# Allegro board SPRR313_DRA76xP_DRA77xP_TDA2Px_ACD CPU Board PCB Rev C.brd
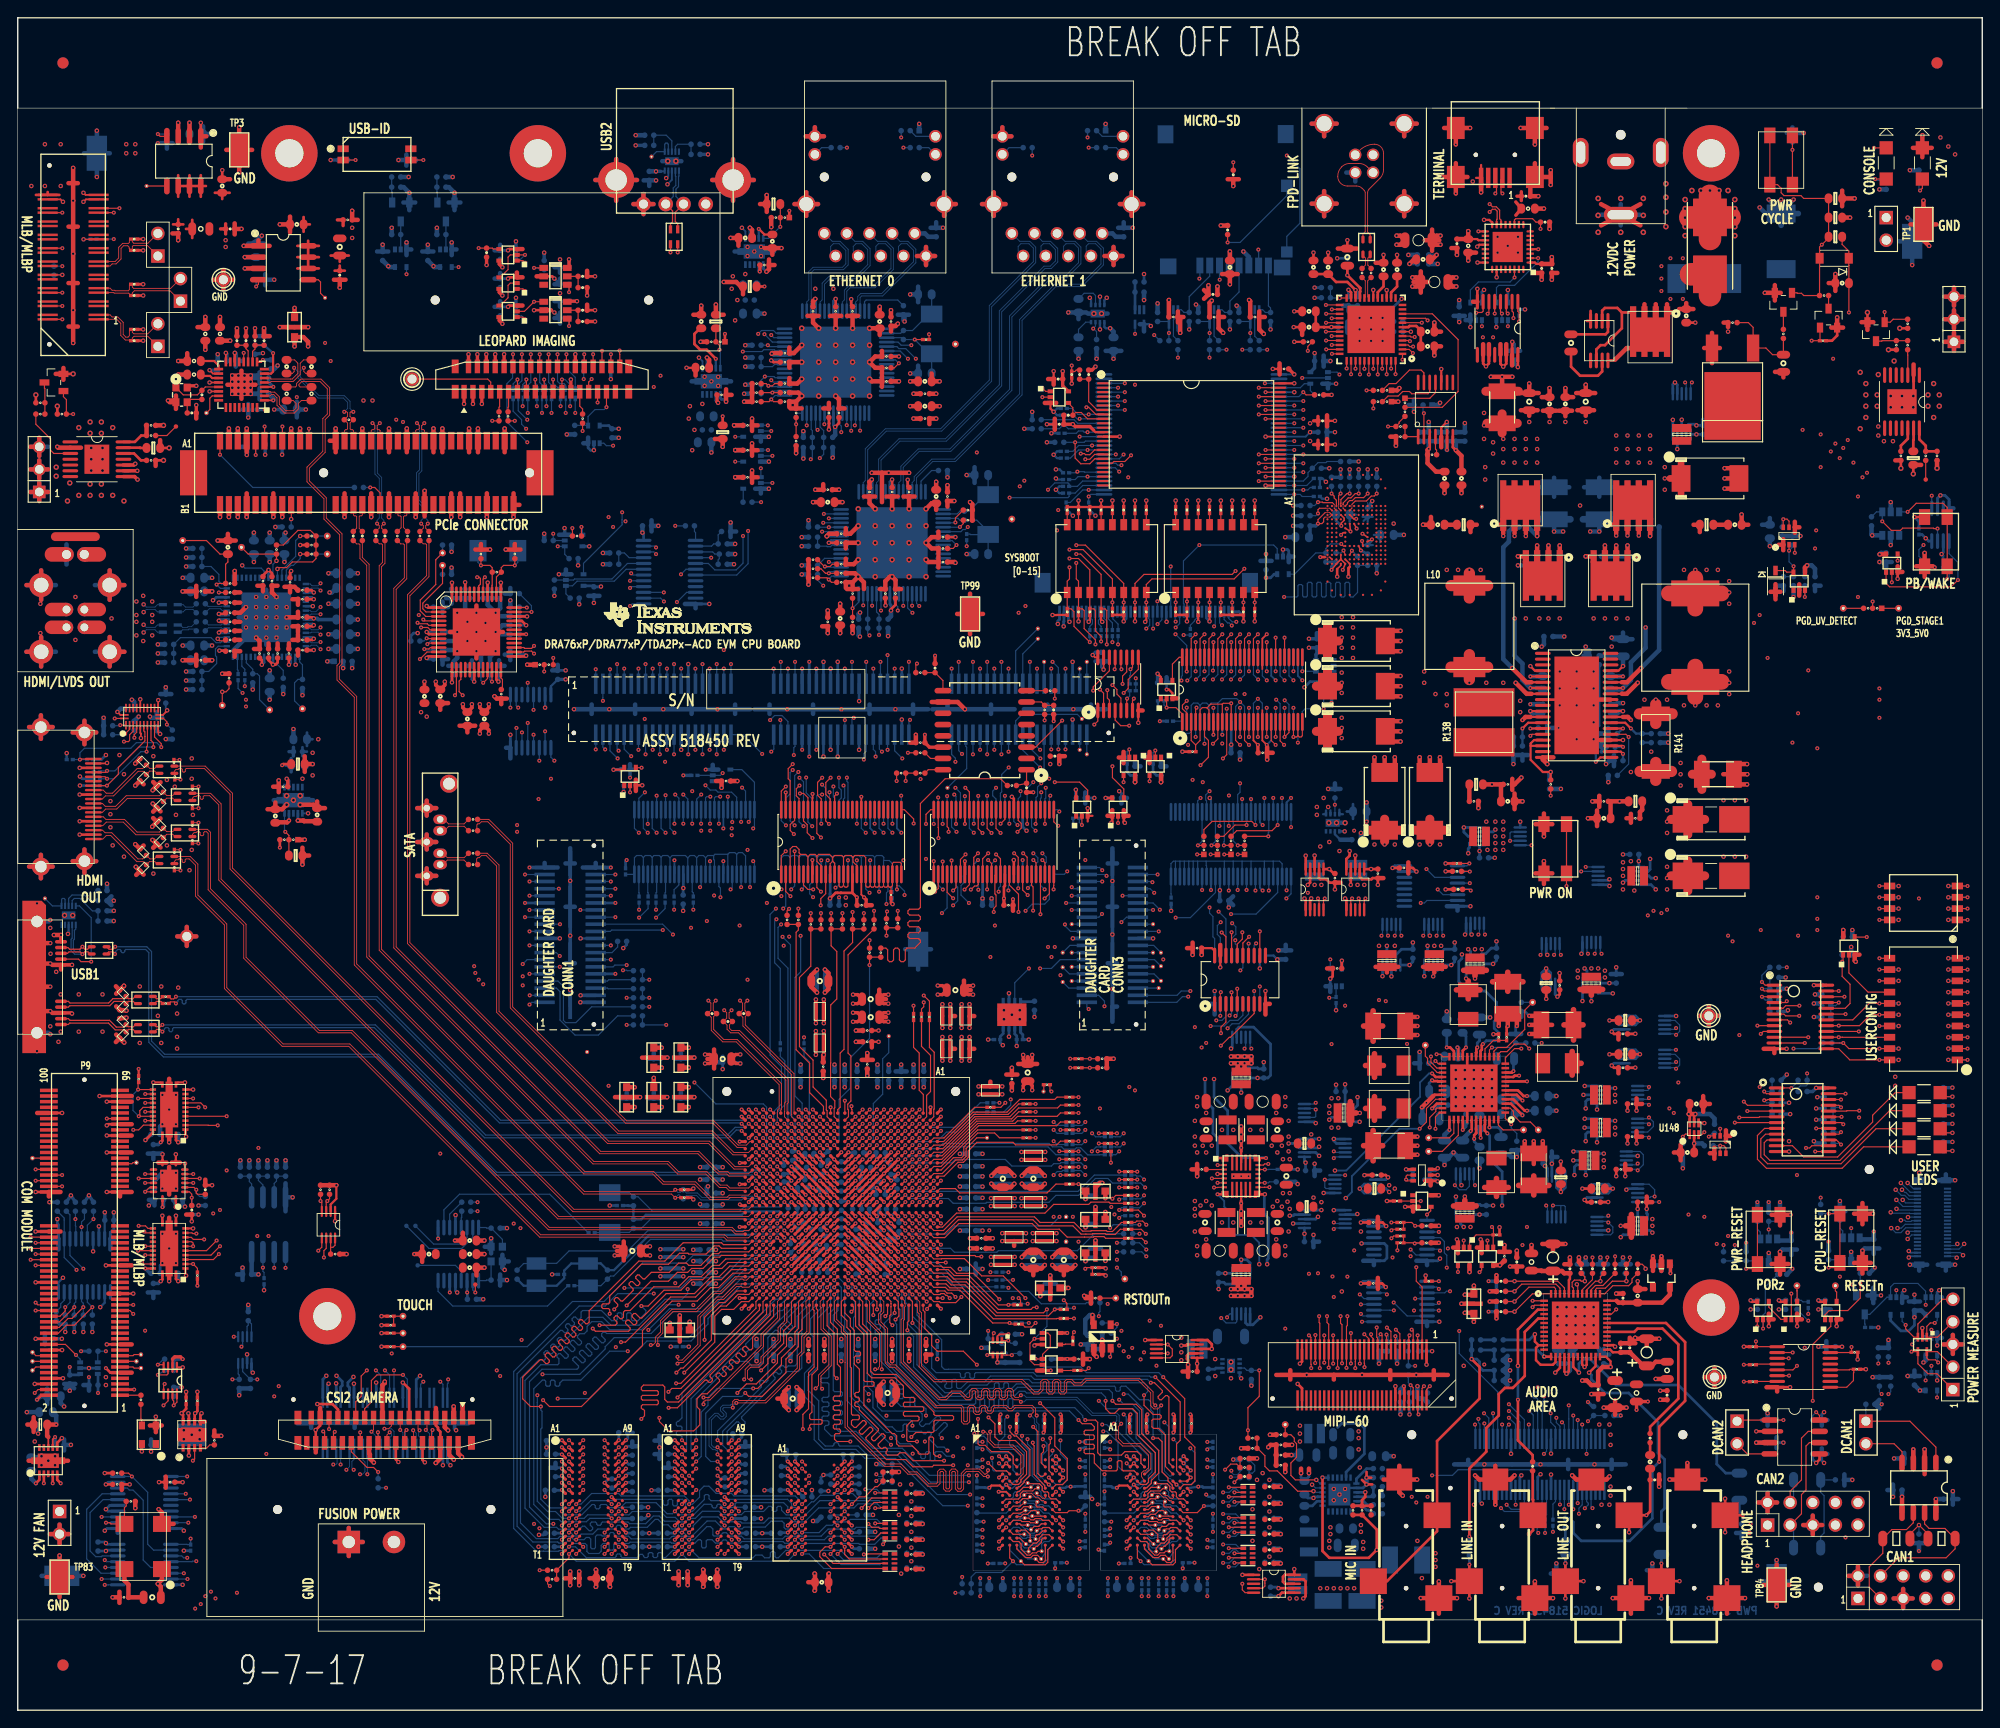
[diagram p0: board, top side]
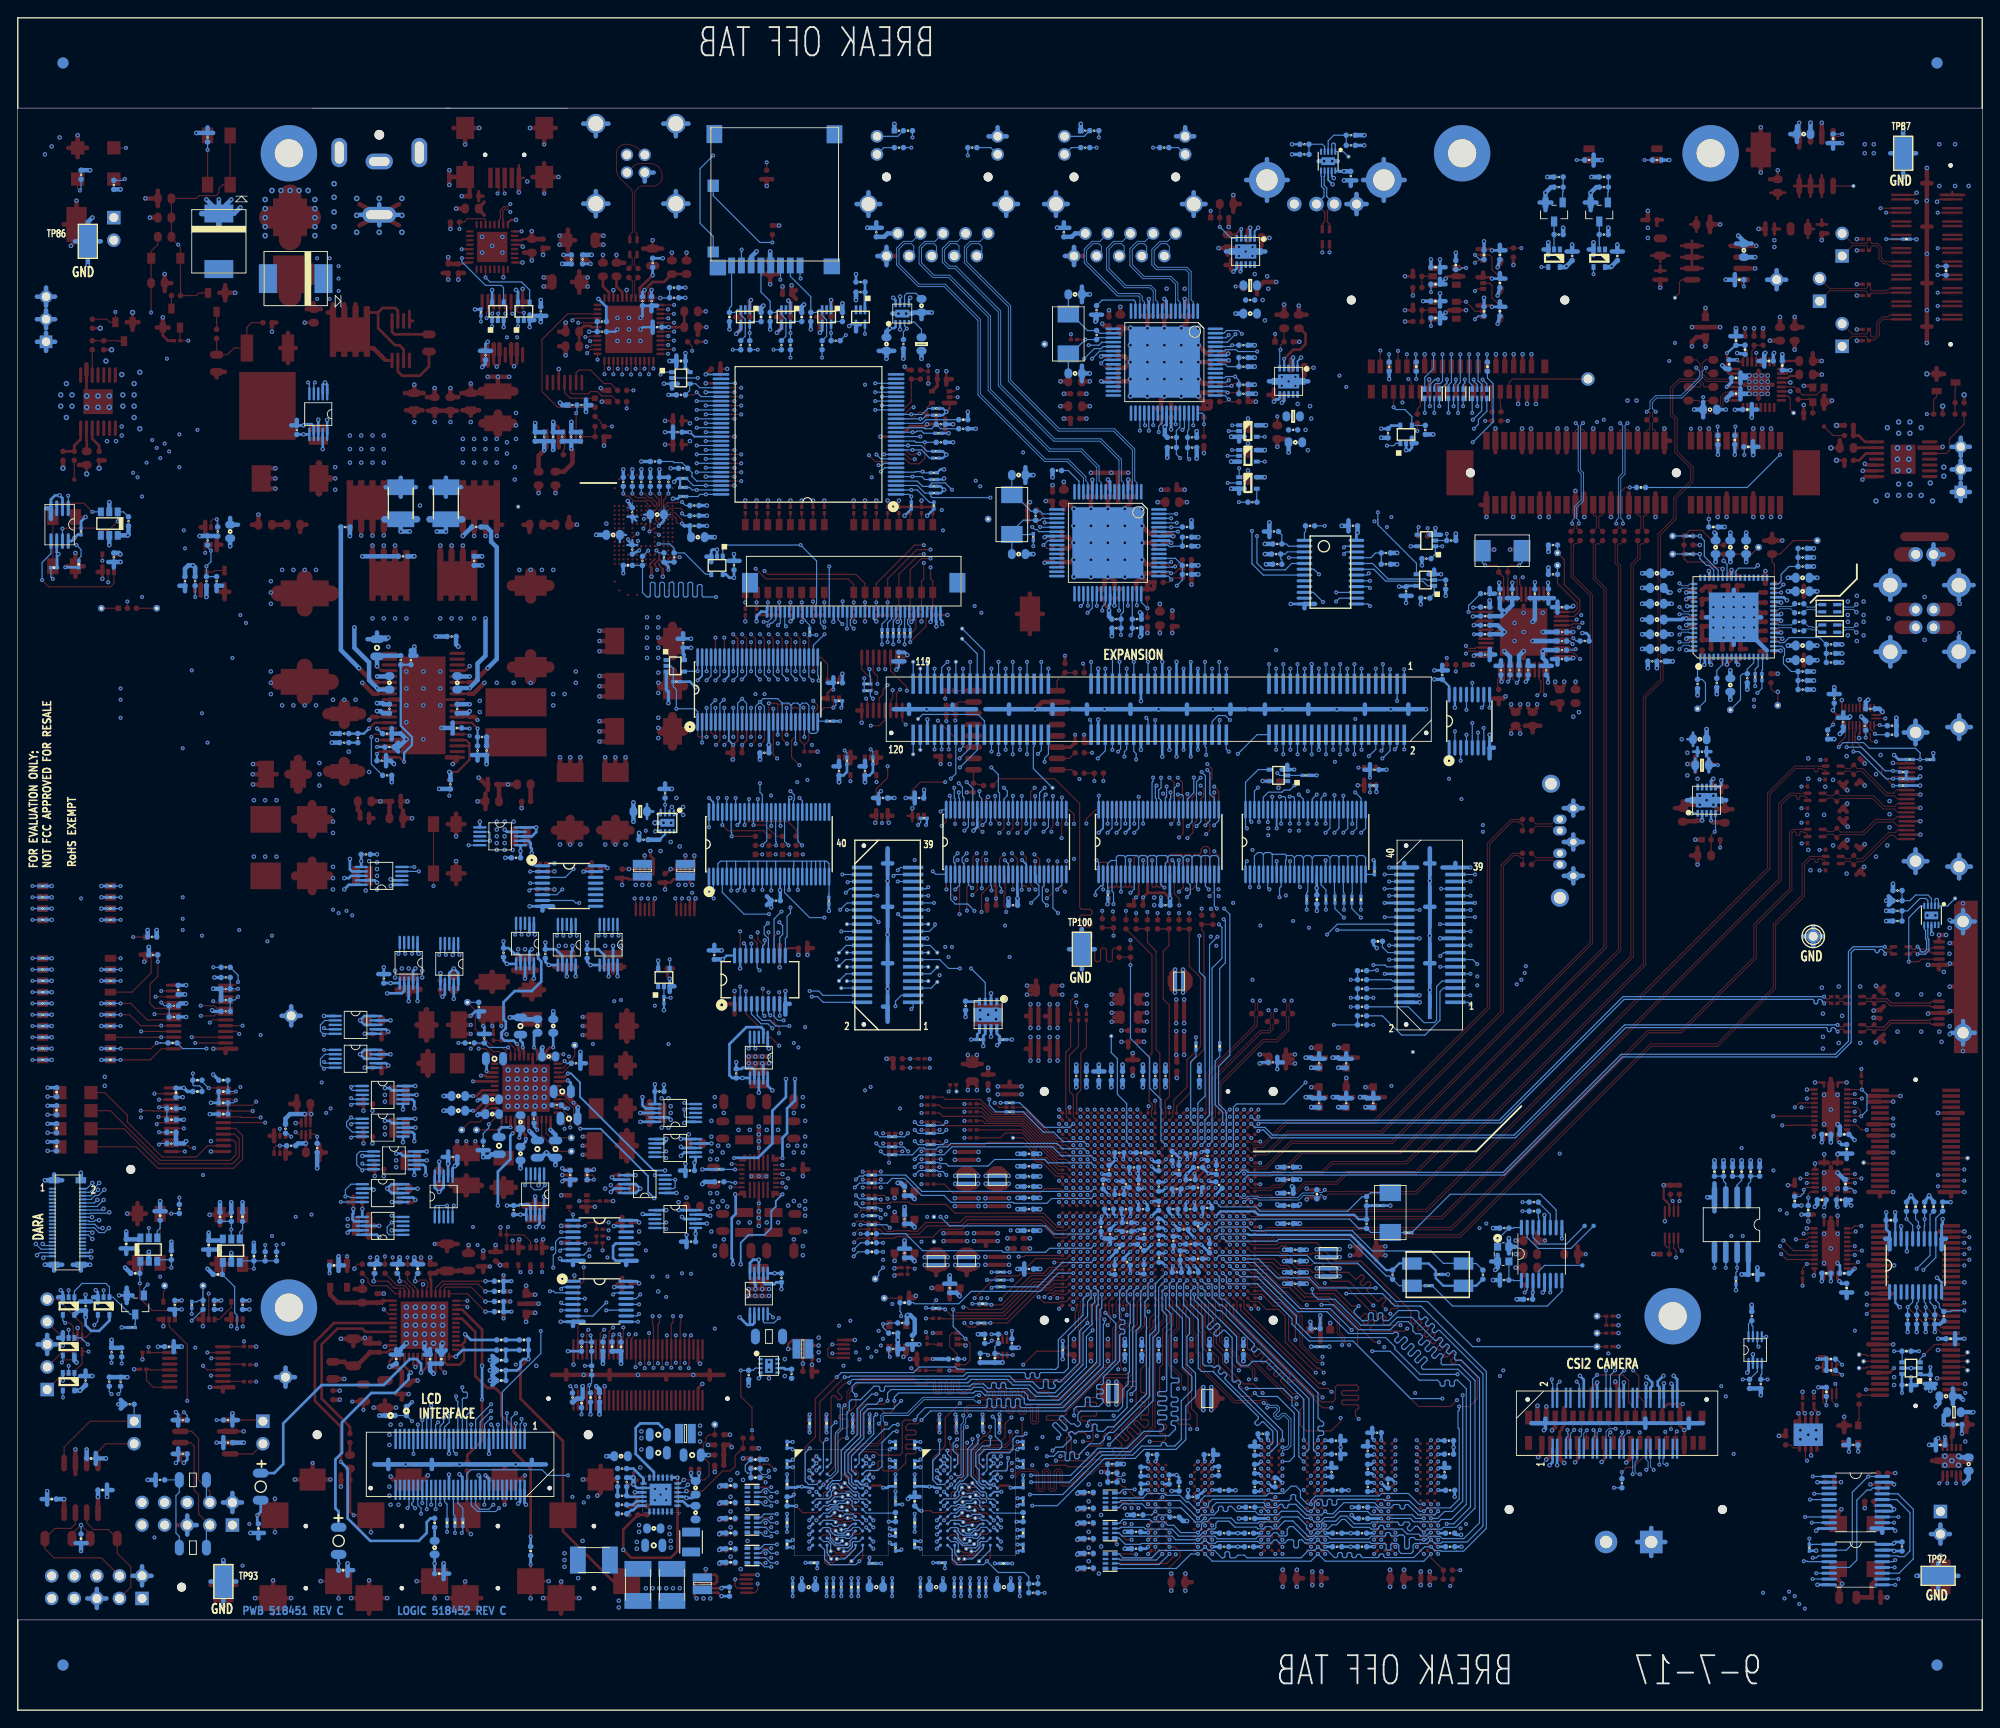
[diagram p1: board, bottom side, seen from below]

Outline 220.85 x 190.37 mm; copper layers: TOP, L2-GND1, L3-SIGNAL, L4-GND2, L5-SIGNAL, L6-GND3, L7-SIGNAL, L8-PWR1, L9-PWR2, L10-SIGNAL, L11-GND4, L12-SIGNAL, L13-GND5, L14-SIGNAL, L15-GND6, BOTTOM. Coordinates in mm from the lower left corner of the outline.
Outline path: 0,180.21 0,190.37 220.85,190.37 220.85,180.21 ; 0,180.21 220.85,180.21 ; 0,180.21 0,10.16 ; 220.85,180.21 220.85,10.16 ; 0,10.16 0,0 220.85,0 220.85,10.16 ; 0,10.16 220.85,10.16

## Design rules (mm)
net group APP_BD_PORZ: nets APP_BD_PORZ H_PORZ
net group CAM_SPI[1]_SCLK: nets CAM_SPI[1]_SCLK N18580530
net group COMQ_MMC0_CMD: nets COMQ_MMC0_CMD H_MMC4_CMD
net group COMQ_MMC0_DAT0: nets COMQ_MMC0_DAT0 H_MMC4_DAT0
net group COMQ_MMC0_DAT1: nets COMQ_MMC0_DAT1 H_MMC4_DAT1
net group COMQ_MMC0_DAT2: nets COMQ_MMC0_DAT2 H_MMC4_DAT2
net group COMQ_MMC0_DAT3: nets COMQ_MMC0_DAT3 H_MMC4_DAT3
net group CON.PCIE_RXN0: nets CON.PCIE_RXN0 H_PCIE_RXN0
net group CON.PCIE_RXP0: nets CON.PCIE_RXP0 H_PCIE_RXP0
net group CON.PCIE_TXN0: nets CON.PCIE_TXN0 H_PCIE_TXN0
net group CON.PCIE_TXP0: nets CON.PCIE_TXP0 H_PCIE_TXP0
net group CON_LCD_GP0[31]: nets CON_LCD_GP0[31] H_GP1[2]_TOUCH_EVT
net group CON_MMC1_DAT3: nets CON_MMC1_DAT3 H_MMC1_D3
net group CONN_USB2_DM: nets CONN_USB2_DM USB_DM_DN1
net group CONN_USB2_DP: nets CONN_USB2_DP USB_DP_DN1
net group CONN_USB_RX0: nets CONN_USB_RXN0 CONN_USB_RXP0
net group CONN_USB_TX0: nets CONN_USB_TXN0 CONN_USB_TXP0
net group DP_CONN_USB1_D: nets CONN_USB1_DM CONN_USB1_DP
net group DP_H_USB2_D: nets H_USB2_DN H_USB2_DP
net group DP_PCI_CONN_REF: nets PCI_CONN_REFN REFCLKN
net group DP_REFCLK: nets PCI_CONN_REFP REFCLKP
net group H_AIC3106_MCLK: nets H_AIC3106_MCLK N17464229
net group H_GP5[0]: nets H_GP5[0] N17038700
net group H_GPMC_A0: nets H_GPMC_A0 VOUT3B_D16
net group H_GPMC_A1: nets H_GPMC_A1 VOUT3B_D17
net group H_GPMC_A2: nets H_GPMC_A2 VOUT3B_D18
net group H_GPMC_A3: nets H_GPMC_A3 VOUT3B_D19
net group H_GPMC_A4: nets H_GPMC_A4 VOUT3B_D20
net group H_GPMC_A5: nets H_GPMC_A5 VOUT3B_D21
net group H_GPMC_A6: nets H_GPMC_A6 VOUT3B_D22
net group H_GPMC_A7: nets H_GPMC_A7 VOUT3B_D23
net group H_GPMC_A8: nets H_GPMC_A8 VOUT3B_HSYNC
net group H_GPMC_A9: nets H_GPMC_A9 VOUT3B_VSYNC
net group H_GPMC_A10: nets H_GPMC_A10 VOUT3B_DE
net group H_GPMC_A19: nets H_GPMC_A19 MMC2_DAT4
net group H_GPMC_A20: nets H_GPMC_A20 MMC2_DAT5
net group H_GPMC_A21: nets H_GPMC_A21 MMC2_DAT6
net group H_GPMC_A22: nets H_GPMC_A22 MMC2_DAT7
net group H_GPMC_A24: nets H_GPMC_A24 MMC2_DAT0
net group H_GPMC_A25: nets H_GPMC_A25 MMC2_DAT1
net group H_GPMC_A26: nets H_GPMC_A26 MMC2_DAT2
net group H_GPMC_A27: nets H_GPMC_A27 MMC2_DAT3
net group H_GPMC_AD0: nets H_GPMC_AD0 VOUT3B_D0
net group H_GPMC_AD1: nets H_GPMC_AD1 VOUT3B_D1
net group H_GPMC_AD2: nets H_GPMC_AD2 VOUT3B_D2
net group H_GPMC_AD3: nets H_GPMC_AD3 VOUT3B_D3
net group H_GPMC_AD4: nets H_GPMC_AD4 VOUT3B_D4
net group H_GPMC_AD5: nets H_GPMC_AD5 VOUT3B_D5
net group H_GPMC_AD6: nets H_GPMC_AD6 VOUT3B_D6
net group H_GPMC_AD7: nets H_GPMC_AD7 VOUT3B_D7
net group H_GPMC_AD8: nets H_GPMC_AD8 VOUT3B_D8
net group H_GPMC_AD9: nets H_GPMC_AD9 VOUT3B_D9
net group H_GPMC_AD10: nets H_GPMC_AD10 VOUT3B_D10
net group H_GPMC_AD11: nets H_GPMC_AD11 VOUT3B_D11
net group H_GPMC_AD12: nets H_GPMC_AD12 VOUT3B_D12
net group H_GPMC_AD13: nets H_GPMC_AD13 VOUT3B_D13
net group H_GPMC_AD14: nets H_GPMC_AD14 VOUT3B_D14
net group H_GPMC_AD15: nets H_GPMC_AD15 VOUT3B_D15
net group H_GPMC_CS1: nets H_GPMC_CS1 MMC2_CMD
net group H_LCD_B0: nets H_LCD_B0 N17468373
net group H_LCD_B1: nets H_LCD_B1 N17468379
net group H_LCD_B2: nets H_LCD_B2 N17468389
net group H_LCD_B3: nets H_LCD_B3 N17468401
net group H_LCD_B4: nets H_LCD_B4 N17468413
net group H_LCD_B5: nets H_LCD_B5 N17468425
net group H_LCD_B6: nets H_LCD_B6 N17468437
net group H_LCD_B7: nets H_LCD_B7 N17468449
net group H_LCD_DE: nets H_LCD_DE N17468701
net group H_LCD_G0: nets H_LCD_G0 N17468461
net group H_LCD_G1: nets H_LCD_G1 N17468473
net group H_LCD_G2: nets H_LCD_G2 N17468485
net group H_LCD_G3: nets H_LCD_G3 N17468497
net group H_LCD_G4: nets H_LCD_G4 N17468509
net group H_LCD_G5: nets H_LCD_G5 N17468521
net group H_LCD_G6: nets H_LCD_G6 N17468533
net group H_LCD_G7: nets H_LCD_G7 N17468545
net group H_LCD_HS: nets H_LCD_HS N17468677
net group H_LCD_PCLK: nets H_LCD_PCLK N17468659
net group H_LCD_R0: nets H_LCD_R0 N17468557
net group H_LCD_R1: nets H_LCD_R1 N17468569
net group H_LCD_R2: nets H_LCD_R2 N17468581
net group H_LCD_R3: nets H_LCD_R3 N17468593
net group H_LCD_R4: nets H_LCD_R4 N17468605
net group H_LCD_R5: nets H_LCD_R5 N17468617
net group H_LCD_R6: nets H_LCD_R6 N17468629
net group H_LCD_R7: nets H_LCD_R7 N17468641
net group H_LCD_VS: nets H_LCD_VS N17468667
net group H_LJCB_CLKN: nets H_LJCB_CLKN SERDES_IN_REFN
net group H_LJCB_CLKP: nets H_LJCB_CLKP SERDES_IN_REFP
net group H_MCA2_AXR0: nets H_MCA2_AXR0 MCA2_AXR0
net group H_MCA2_AXR1: nets H_MCA2_AXR1 MCA2_AXR1
net group H_MCA2_AXR2: nets H_MCA2_AXR2 MCA2_AXR2
net group H_MCA2_AXR3: nets H_MCA2_AXR3 MCA2_AXR3
net group H_MCA2_AXR4: nets H_MCA2_AXR4 MCA2_AXR4
net group H_MCA2_AXR5: nets H_MCA2_AXR5 MCA2_AXR5
net group H_MCA2_AXR6: nets H_MCA2_AXR6 MCA2_AXR6
net group H_MCA2_AXR7: nets H_MCA2_AXR7 MCA2_AXR7
net group H_MCA6_AXR0: nets H_MCA6_AXR0 MCA6_AXR0
net group H_MCA6_AXR1: nets H_MCA6_AXR1 MCA6_AXR1
net group H_MCA7_AXR0: nets H_MCA7_AXR0 MCA7_AXR0
net group H_MCA7_AXR1: nets H_MCA7_AXR1 MCA7_AXR1
net group H_MDIO_D: nets H_MDIO_D VIN[4]B_D[0]
net group H_MDIO_MCLK: nets H_MDIO_MCLK VIN[4]B_CLK1
net group H_MMC1_CMD: nets CON_MMC1_CMD H_MMC1_CMD
net group H_MMC1_D0: nets CON_MMC1_DAT0 H_MMC1_D0
net group H_MMC1_D1: nets CON_MMC1_DAT1 H_MMC1_D1
net group H_MMC1_D2: nets CON_MMC1_DAT2 H_MMC1_D2
net group H_MMC3_CLK: nets H_MMC3_CLK N18551238
net group H_POWERHOLD_CLK: nets H_POWERHOLD_CLK N17468893
net group H_RGMII0_RXD0: nets EMAC[0]_RXD0 H_RGMII0_RXD0
net group H_RGMII0_RXD1: nets EMAC[0]_RXD1 H_RGMII0_RXD1
net group H_RGMII0_RXD2: nets EMAC[0]_RXD2 H_RGMII0_RXD2
net group H_RSTOUTN: nets H_RSTOUTN N20753149
net group H_SATA_RXN0: nets CON.SATA_RXN0 H_SATA_RXN0
net group H_SATA_RXP0: nets CON.SATA_RXP0 H_SATA_RXP0
net group H_SATA_TXN0: nets CON.SATA_TXN0 H_SATA_TXN0
net group H_SATA_TXP0: nets CON.SATA_TXP0 H_SATA_TXP0
net group H_UART3_RXD: nets H_UART3_RXD VIN[4]B_D[1]
net group H_UART3_TXD: nets H_UART3_TXD VIN[4]B_D[2]
net group H_VIN2_DE: nets H_VIN2_DE VIN[2]A_DE0
net group H_VIN[5]A_D[8]: nets H_VIN[5]A_D[8] N18588548
net group H_VIN[5]A_D[9]: nets H_VIN[5]A_D[9] N18588505
net group H_VIN[5]A_D[10]: nets H_VIN[5]A_D[10] N18588483
net group H_VIN[5]A_D[11]: nets H_VIN[5]A_D[11] N18588440
net group H_XI_OSC0: nets H_XI_OSC0 XI_OSC0
net group H_XI_OSC1: nets H_XI_OSC1 XI_OSC1
net group HDMI_CT_HPD: nets HDMI_CT_HPD N18586717
net group HDMI_LS_OE: nets HDMI_LS_OE N18586695
net group HDMI_TX0+: nets H_HDMI_DY0 HDMI_TX0+
net group HDMI_TX0-: nets H_HDMI_DX0 HDMI_TX0-
net group HDMI_TX1+: nets H_HDMI_DY1 HDMI_TX1+
net group HDMI_TX1-: nets H_HDMI_DX1 HDMI_TX1-
net group HDMI_TX2+: nets H_HDMI_DY2 HDMI_TX2+
net group HDMI_TX2-: nets H_HDMI_DX2 HDMI_TX2-
net group HDMI_TXC+: nets H_HDMI_CLKY HDMI_TXC+
net group HDMI_TXC-: nets H_HDMI_CLKX HDMI_TXC-
net group I2C2_SCL_PM: nets I2C2_SCL_PM N17038308
net group I2C2_SDA_PM: nets I2C2_SDA_PM N17038335
net group P0_TRD[0]: nets P0_TRD[0]N P0_TRD[0]P
net group P0_TRD[1]: nets P0_TRD[1]N P0_TRD[1]P
net group P0_TRD[2]: nets P0_TRD[2]N P0_TRD[2]P
net group P0_TRD[3]: nets P0_TRD[3]N P0_TRD[3]P
net group P1_TRD[0]: nets P1_TRD[0]N P1_TRD[0]P
net group P1_TRD[1]: nets P1_TRD[1]N P1_TRD[1]P
net group P1_TRD[2]: nets P1_TRD[2]N P1_TRD[2]P
net group P1_TRD[3]: nets P1_TRD[3]N P1_TRD[3]P
net group SPI[1]_SCLK: nets N18580585 SPI[1]_SCLK
net group USB_AC_TX0: nets USB_AC_TXN0 USB_AC_TXP0
net group XI_PHY0: nets N17030260 XI_PHY0
net group XI_PHY1: nets N17032852 XI_PHY1
net group 90-OHM: nets CONN_USB_D+ CONN_USB_D- H_USB1_DN H_USB1_DP USB_DM_DN2 USB_DP_DN2
net group 90-OHMUSB_PH: nets H_USB3_RXN H_USB3_RXP H_USB3_TXN H_USB3_TXP
net group 100-OHM: nets CON.PCIE_RXN1 CON.PCIE_RXP1 CON.PCIE_TXN1 CON.PCIE_TXP1 D1_0N D1_0P D1_1N D1_1P D1_ACOUT0N D1_ACOUT0P D1_ACOUT1N D1_ACOUT1P D1_OUT0N D1_OUT0P D1_OUT1N D1_OUT1P DISP1_CLK+ DISP1_CLK- DISP1_D0+ DISP1_D0- DISP1_D1+ DISP1_D1- DISP1_D2+ DISP1_D2- H_MLBP_CLKN H_MLBP_CLKP H_MLBP_DN H_MLBP_DP H_MLBP_SIGN H_MLBP_SIGP H_PCIE_RXN1 H_PCIE_RXP1 H_PCIE_TXN1 H_PCIE_TXP1
net group AIC_BCLK: nets AIC_BCLK AIC_MCA3_ACLKX H_MCA3_ACLKX N18587966
net group AIC_DIN: nets AIC_DIN AIC_MCA3_AXR0 H_MCA3_AXR0 N18588000
net group AIC_DOUT: nets AIC_DOUT AIC_MCA3_AXR1 H_MCA3_AXR1 N18588017
net group AIC_MCA3_AFSX: nets AIC_MCA3_AFSX AIC_WCLK H_MCA3_AFSX N18587983
net group AQSPI1_D[0]: nets AQSPI1_D[0] H_GPMC_A16 R_QSPI1_D[0]
net group AQSPI1_D[1]: nets AQSPI1_D[1] H_GPMC_A17 R_QSPI1_D[1]
net group AQSPI1_D[2]: nets AQSPI1_D[2] H_GPMC_A15 R_QSPI1_D[2]
net group AQSPI1_D[3]: nets AQSPI1_D[3] H_GPMC_A14 R_QSPI1_D[3]
net group AQSPI1_RTCLK: nets AQSPI1_RTCLK AQSPI1_SCLK H_GPMC_A13 H_GPMC_A18 R_QSPI1_SCLK
net group CAMERA_CLK: nets CAMERA_CLK H_VIN2_CLK N17534968 VIN[2]A_CLK
net group CAMERA_D0: nets CAMERA_D0 H_VIN2_D0 N17535203 VIN[2]A_D[0]
net group CAMERA_D1: nets CAMERA_D1 H_VIN2_D1 N17535194 VIN[2]A_D[1]
net group CAMERA_D2: nets CAMERA_D2 H_VIN2_D2 N17535156 VIN[2]A_D[2]
net group CAMERA_D3: nets CAMERA_D3 H_VIN2_D3 N17535152 VIN[2]A_D[3]
net group CAMERA_D4: nets CAMERA_D4 H_VIN2_D4 N17535143 VIN[2]A_D[4]
net group CAMERA_D5: nets CAMERA_D5 H_VIN2_D5 N17535134 VIN[2]A_D[5]
net group CAMERA_D6: nets CAMERA_D6 H_VIN2_D6 N17535125 VIN[2]A_D[6]
net group CAMERA_D7: nets CAMERA_D7 H_VIN2_D7 N17535102 VIN[2]A_D[7]
net group CAMERA_D8: nets CAMERA_D8 H_VIN2_D8 N17535093 VIN[2]A_D[8]
net group CAMERA_D9: nets CAMERA_D9 H_VIN2_D9 N17535084 VIN[2]A_D[9]
net group CAMERA_D10: nets CAMERA_D10 H_VIN2_D10 N17535075 VIN[2]A_D[10]
net group CAMERA_D11: nets CAMERA_D11 H_VIN2_D11 N17535052 VIN[2]A_D[11]
net group CAMERA_HSYNC: nets CAMERA_HSYNC H_VIN2_HSYNC N17240462 N17535025 VIN[2]A_HSYNC
net group CAMERA_VSYNC: nets CAMERA_VSYNC H_VIN2_VSYNC N17535002 VIN[2]A_VSYNC
net group COMQ_MMC0_CLK: nets COMQ_MMC0_CLK H_MMC4_CLK N18582457
net group CON_MMC1_CLK: nets CON_MMC1_CLK H_MMC1_CLK N18551205
net group CSI2_0: nets H_CSI2_0_DX0 H_CSI2_0_DX1 H_CSI2_0_DX2 H_CSI2_0_DX3 H_CSI2_0_DX4 H_CSI2_0_DY0 H_CSI2_0_DY1 H_CSI2_0_DY2 H_CSI2_0_DY3 H_CSI2_0_DY4
net group CSI2_1: nets H_CSI2_1_DX0 H_CSI2_1_DX1 H_CSI2_1_DX2 H_CSI2_1_DY0 H_CSI2_1_DY1 H_CSI2_1_DY2
net group DDR1_DATA0: nets H_DDR1_D0 H_DDR1_D1 H_DDR1_D2 H_DDR1_D3 H_DDR1_D4 H_DDR1_D5 H_DDR1_D6 H_DDR1_D7 H_DDR1_DQM0 H_DDR1_DQS0_N H_DDR1_DQS0_P
net group DDR1_DATA1: nets H_DDR1_D8 H_DDR1_D9 H_DDR1_D10 H_DDR1_D11 H_DDR1_D12 H_DDR1_D13 H_DDR1_D14 H_DDR1_D15 H_DDR1_DQM1 H_DDR1_DQS1_N H_DDR1_DQS1_P
net group DDR1_DATA2: nets H_DDR1_D16 H_DDR1_D17 H_DDR1_D18 H_DDR1_D19 H_DDR1_D20 H_DDR1_D21 H_DDR1_D22 H_DDR1_D23 H_DDR1_DQM2 H_DDR1_DQS2_N H_DDR1_DQS2_P
net group DDR1_DATA3: nets H_DDR1_D24 H_DDR1_D25 H_DDR1_D26 H_DDR1_D27 H_DDR1_D28 H_DDR1_D29 H_DDR1_D30 H_DDR1_D31 H_DDR1_DQM3 H_DDR1_DQS3_N H_DDR1_DQS3_P
net group DDR1_DATA_ECC: nets H_DDR1_ECC_D0 H_DDR1_ECC_D1 H_DDR1_ECC_D2 H_DDR1_ECC_D3 H_DDR1_ECC_D4 H_DDR1_ECC_D5 H_DDR1_ECC_D6 H_DDR1_ECC_D7 H_DDR1_ECC_DQM H_DDR1_ECC_DQS_N H_DDR1_ECC_DQS_P
net group DDR2_DATA0: nets H_DDR2_D0 H_DDR2_D1 H_DDR2_D2 H_DDR2_D3 H_DDR2_D4 H_DDR2_D5 H_DDR2_D6 H_DDR2_D7 H_DDR2_DQM0 H_DDR2_DQS0_N H_DDR2_DQS0_P
net group DDR2_DATA1: nets H_DDR2_D8 H_DDR2_D9 H_DDR2_D10 H_DDR2_D11 H_DDR2_D12 H_DDR2_D13 H_DDR2_D14 H_DDR2_D15 H_DDR2_DQM1 H_DDR2_DQS1_N H_DDR2_DQS1_P
net group DDR2_DATA2: nets H_DDR2_D16 H_DDR2_D17 H_DDR2_D18 H_DDR2_D19 H_DDR2_D20 H_DDR2_D21 H_DDR2_D22 H_DDR2_D23 H_DDR2_DQM2 H_DDR2_DQS2_N H_DDR2_DQS2_P
net group DDR2_DATA3: nets H_DDR2_D24 H_DDR2_D25 H_DDR2_D26 H_DDR2_D27 H_DDR2_D28 H_DDR2_D29 H_DDR2_D30 H_DDR2_D31 H_DDR2_DQM3 H_DDR2_DQS3_N H_DDR2_DQS3_P
net group EMAC[0]_TXC: nets EMAC[0]_TXC H_RGMII0_TXC N17470760 VIN[4]B_D[3]
net group EMAC[0]_TXCTL: nets EMAC[0]_TXCTL H_RGMII0_TXCTL N17470772 VIN[4]B_D[4]
net group EMAC[0]_TXD0: nets EMAC[0]_TXD0 H_RGMII0_TXD0 N17470784
net group EMAC[0]_TXD1: nets EMAC[0]_TXD1 H_RGMII0_TXD1 N17470792 VIN[4]B_VSYNC1
net group EMAC[0]_TXD2: nets EMAC[0]_TXD2 H_RGMII0_TXD2 N17470802 VIN[4]B_HSYNC1
net group EMAC[0]_TXD3: nets EMAC[0]_TXD3 H_RGMII0_TXD3 N17470810
net group EMAC[1]_TXC: nets CAMERA_D12 EMAC[1]_TXC H_VIN2_D12 N17535043 N1746820385 VIN[2]A_D[12]
net group EMAC[1]_TXCTL: nets CAMERA_D13 EMAC[1]_TXCTL H_VIN2_D13 N17535034 N1746820386 VIN[2]A_D[13]
net group EMAC[1]_TXD0: nets EMAC[1]_TXD0 H_VIN2_D17 N1746820390 VIN[2]A_D[17]
net group EMAC[1]_TXD1: nets EMAC[1]_TXD1 H_VIN2_D16 N1746820389 VIN[2]A_D[16]
net group EMAC[1]_TXD2: nets EMAC[1]_TXD2 H_VIN2_D15 N1746820388 VIN[2]A_D[15]
net group EMAC[1]_TXD3: nets EMAC[1]_TXD3 H_VIN2_D14 N1746820387 VIN[2]A_D[14]
net group FPD_DOUT+: nets FPD_DOUT+ N17132449 N17132477
net group FPD_DOUT-: nets FPD_DOUT- N17132490 N17132501
net group H_GPMC_A23: nets H_GPMC_A23 MMC2_CLK N16856648
net group H_GPMC_CS3: nets H_GPMC_CS3 VOUT3B_CLK VOUT3B_CLK_CLEANED
net group H_MCA2_ACLKX: nets H_MCA2_ACLKX MCA2_ACLKX N18587580
net group H_MCA2_AFSX: nets H_MCA2_AFSX MCA2_AFSX N18608628
net group H_MCA6_CLKX: nets H_MCA6_CLKX MCA6_ACLKX N18586871
net group H_MCA6_FSX: nets H_MCA6_FSX MCA6_AFSX N18586893
net group H_MCA7_CLKX: nets H_MCA7_CLKX MCA7_CLKX N18586939
net group H_MCA7_FSX: nets H_MCA7_FSX MCA7_FSX N18586956
net group H_RGMII0_RXC: nets EMAC[0]_RXC H_RGMII0_RXC VIN[4]B_D[5]
net group H_RGMII0_RXCTL: nets EMAC[0]_RXCTL H_RGMII0_RXCTL VIN[4]B_D[6]
net group H_RGMII0_RXD3: nets EMAC[0]_RXD3 H_RGMII0_RXD3 VIN[4]B_D[7]
net group H_SPI2_CS0N: nets H_SPI2_CS0N SPI[2]_CS[0]N UART3_RTS
net group H_SPI2_MISO: nets H_SPI2_MISO SPI[2]_MISO UART3_TXD
net group H_SPI2_MOSI: nets H_SPI2_MOSI SPI[2]_MOSI UART3_CTS
net group H_SPI2_SCLK: nets H_SPI2_SCLK N18608535 SPI[2]_SCLK UART3_RXD
net group H_SPI[1]_CS[0]N: nets H_CAM_SPI[1]_CS[0]N H_SPI[1]_CS[0]N N17470942
net group H_SPI[1]_MISO: nets H_CAM_SPI[1]_MISO H_SPI[1]_MISO N17470990
net group H_SPI[1]_MOSI: nets H_CAM_SPI[1]_MOSI H_SPI[1]_MOSI N17470980
net group H_VIN2_D18: nets EMAC[1]_RXC H_VIN2_D18 VIN[2]A_D[18]
net group H_VIN2_D19: nets EMAC[1]_RXCTL H_VIN2_D19 VIN[2]A_D[19]
net group H_VIN2_D20: nets EMAC[1]_RXD3 H_VIN2_D20 VIN[2]A_D[20]
net group H_VIN2_D21: nets EMAC[1]_RXD2 H_VIN2_D21 VIN[2]A_D[21]
net group H_VIN2_D22: nets EMAC[1]_RXD1 H_VIN2_D22 VIN[2]A_D[22]
net group H_VIN2_D23: nets EMAC[1]_RXD0 H_VIN2_D23 VIN[2]A_D[23]
net group H_XREF_CLK1: nets H_XREF_CLK1 MCA6_AHCLKX N17464210
net group MMC3: nets H_MMC3_CMD H_MMC3_D0 H_MMC3_D1 H_MMC3_D2 H_MMC3_D3 H_MMC3_D4 H_MMC3_D5
net group PWR: nets AIC_AVDD_DAC3.3 AIC_DRVDD3.3 AIC_DVDD3.3 AIC_IOVDD3.3 GA1 GA2 GB1 GB2 LDOVANA N16769518 N16769806 N16769938 N16770060 N16770184 N16770544 N16770800 N16771006 N16771022 N16771108 N16771210 N16833803 N16833813 N17024348 N17024526 N17036157 N17132279 N17132316 N17132397 N17132537 N17213075 N17213086 N17485295 N17493600 N17493609 N17523122 N17523441 N17523739 N17523799 N17533979 N20753978 PHA PHB VBUS_USB1 VCAP_VBBLDO_DSPEVE VCAP_VBBLDO_GPU VCAP_VBBLDO_IVA VCAP_VBBLDO_MPU VCAP_VDDRAM_CORE1 VCAP_VDDRAM_CORE2 VCAP_VDDRAM_CORE3 VCAP_VDDRAM_CORE4 VCAP_VDDRAM_CORE5 VCAP_VDDRAM_DSPEVE1 VCAP_VDDRAM_DSPEVE2 VCAP_VDDRAM_GPU VCAP_VDDRAM_IVA VCAP_VDDRAM_MPU1 VCAP_VDDRAM_MPU2 VDAC_3V3 VDD18_DISP1 VDD33_DSU921 VDD_CDCEL925 VDDI_MMC2 VDDIO_DSU921 VHDMI_5V0 VIO_3V6 VIO_IN_3V3 VPP VPP_EN VSSA_OSC0 VSSA_OSC1 ZQ_DBYTE1 ZQ_DBYTE2 ZQ_DBYTE3 ZQ_DBYTE4 ZQ_DBYTE4_1
net group R_QSPI1_CS[0]: nets AQSPI1_CS[0] H_GPMC_CS2 R_QSPI1_CS[0]
net group VIN1: nets H_VIN1_D0 H_VIN1_D1 H_VIN1_D2 H_VIN1_D3 H_VIN1_D4 H_VIN1_D5 H_VIN1_D6 H_VIN1_D7 H_VIN1_D8 H_VIN1_D9 H_VIN1_D10 H_VIN1_D11 H_VIN1_D12 H_VIN1_D13 H_VIN1_D14 H_VIN1_D15 H_VIN1_D16 H_VIN1_D17 H_VIN1_D18 H_VIN1_D19 H_VIN1_D20 H_VIN1_D21 H_VIN1_D22 H_VIN1_D23 H_VIN1_DE H_VIN1_HSYNC H_VIN1_VSYNC H_VIN1A_CLK H_VIN1B_CLK
net group VIN4_5: nets H_VIN[5]A_D[12] H_VIN[5]A_D[13] H_VIN[5]A_D[14] H_VIN[5]A_D[15]

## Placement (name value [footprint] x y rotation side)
C1  0.1uF  [C402-25]  37.08 167.64 0 top
C2  10uF  [C603-35X45]  31.37 167.13 180 top
C3  10uF  [C603-35X45]  22.99 171.45 90 top
C4  0.1uF  [C402-25]  169.54 170.31 0 top
C5  0.1uF  [C402-25]  23.88 166.62 0 top
C6  2.2uF  [C603-35X45]  81.79 165.61 180 top
C7  10uF  [C1206-40X70]  157.48 165.35 0 top
C8  2.2uF  [C603-35X45]  84.84 165.23 270 top
C9  0.1uF  [C402-25]  161.8 164.97 270 top
C10  4.7uF  [C603-35X45]  163.07 164.72 270 top
C11  10uF  [C805-35X60]  149.48 163.45 90 top
C12  NP  [C402-25]  83.95 162.56 0 top
C13  10uF  [C603-35X45]  136.27 162.31 270 top
C14  4.7uF  [C603-35X45]  147.32 162.31 90 top
C15  0.1uF  [C402-25]  171.32 162.18 270 top
C16  0.1uF  [C402-25]  172.47 162.18 270 top
C17  4.7uF  [C603-35X45]  153.54 162.05 90 top
C18  4.7uF  [C603-35X45]  155.07 162.05 90 top
C19  0.1uF  [C402-25]  151.13 161.67 90 top
C20  0.1uF  [C402-25]  152.15 161.67 90 top
C21  10uF  [C1206-40X70]  159.26 160.66 180 top
C22  0.1uF  [C402-25]  134.37 159.26 180 top
C23  1000pF  [C402-25]  89.41 157.35 270 top
C24  1000pF  [C402-25]  91.95 157.35 270 top
C25  1000pF  [C402-25]  93.85 157.35 270 top
C26  0.1uF  [C402-25]  129.92 156.72 0 top
C27  0.1uF  [C402-25]  134.49 156.72 0 top
C28  0.1uF  [C402-25]  139.06 156.72 0 top
C29  2.2uF  [C603-35X45]  76.83 156.21 90 top
C30  10uF  [C603-35X45]  96.9 156.21 270 top
C31  0.01uF  [C402-25]  98.17 156.21 270 top
C32  4.7uF  [C603-35X45]  145.16 155.57 180 top
C33  4.7uF  [C603-35X45]  158.5 155.07 0 top
C34  10uF  [C603-35X45]  21.08 154.81 90 top
C35  0.22uF  [C603-35X45]  205.1 160.53 180 top
C36  4.7uF  [C603-35X45]  158.5 153.42 0 top
C37  0.22uF  [C603-35X45]  187.58 156.84 270 top
C38  1000pF  [C402-25]  86.23 152.65 0 top
C39  1000pF  [C402-25]  97.66 152.27 180 top
C40  4.7uF  [C805-35X60]  198.5 151.51 270 top
C41  10uF  [C603-35X45]  19.81 151.76 180 top
C42  1000pF  [C402-25]  86.23 151.64 0 top
C43  0.1uF  [C603-35X45]  30.23 151.13 270 top
C44  0.1uF  [C603-35X45]  33.02 151.13 270 top
C45  2.2uF  [C603-35X45]  76.96 151 180 top
C46  0.1uF  [C402-25]  142.37 150.88 180 top
C47  2.2uF  [C805-35X60]  174.62 153.8 270 top
C48  10uF  [C603-35X45]  19.81 150.24 180 top
C49  0.1uF  [C402-25]  116.97 149.73 180 top
C50  1000pF  [C402-25]  97.66 149.48 180 top
C51  10uF  [C603-35X45]  101.98 149.48 0 top
C52  0.1uF  [C603-35X45]  30.23 148.08 270 top
C53  0.1uF  [C603-35X45]  33.02 148.08 270 top
C54  0.01uF  [C402-25]  101.98 148.08 0 top
C55  NP  [C402-25]  20.7 147.96 90 top
C56  NP  [C402-25]  79.12 147.96 0 top
C57  1uF  [C805-35X60]  169.93 147.19 90 top
C58  1uF  [C805-35X60]  176.28 147.19 90 top
C59  0.1uF  [C603-35X45]  172.21 146.94 90 top
C60  0.1uF  [C603-35X45]  173.99 146.94 90 top
C61  10uF  [C603-35X45]  101.98 146.69 0 top
C62  4.7uF  [C1210-70X102]  166.88 146.56 90 top
C63  1000pF  [C402-25]  91.19 145.92 90 top
C64  1000pF  [C402-25]  92.33 145.92 90 top
C65  0.01uF  [C402-25]  101.98 145.29 0 top
C66  0.01uF  [C402-25]  146.69 145.03 0 top
C67  0.01uF  [C402-25]  117.09 144.65 180 top
C68  0.1uF  [C402-25]  82.04 144.53 0 top
C69  0.01uF  [C402-25]  146.69 142.37 0 top
C70  0.1uF  [C402-25]  82.04 141.73 0 top
C71  0.1uF  [C402-25]  82.04 138.68 0 top
C72  100uF  [C7343-84X118]  190.25 138.56 0 top
C73  0.01uF  [C402-25]  91.06 137.29 180 top
C74  1000pF  [C402-25]  95.76 137.03 270 top
C75  1000pF  [C402-25]  98.3 137.03 270 top
C76  1000pF  [C402-25]  100.2 137.03 270 top
C77  10uF  [C603-35X45]  103.25 136.53 270 top
C78  0.01uF  [C402-25]  104.52 136.53 270 top
C79  10uF  [C603-35X45]  91.06 135.89 180 top
C80  330pF  [C603-35X45]  159.64 133.35 0 top
C81  330pF  [C603-35X45]  193.04 133.35 180 top
C82  0.1uF  [C402-25]  37.72 132.08 90 top
C83  1000pF  [C402-25]  92.58 132.33 0 top
C84  0.1uF  [C402-25]  38.73 132.08 90 top
C85  0.1uF  [C402-25]  42.67 132.08 90 top
C86  0.1uF  [C402-25]  43.81 132.08 90 top
C87  1000pF  [C402-25]  104.01 131.95 180 top
C88  1000pF  [C402-25]  92.58 131.32 0 top
C89  10uF  [C603-35X45]  23.62 130.81 90 top
C90  1000pF  [C402-25]  104.01 129.16 180 top
C91  0.01uF  [C402-25]  27.56 127 270 top
C92  0.1uF  [C402-25]  28.57 127 270 top
C93  0.1uF  [C402-25]  30.61 126.87 270 top
C94  0.1uF  [C402-25]  32 125.98 180 top
C95  0.01uF  [C402-25]  20.57 125.86 180 top
C96  1000pF  [C402-25]  97.54 125.6 90 top
C97  1000pF  [C402-25]  98.68 125.6 90 top
C98  0.1uF  [C402-25]  32 124.97 180 top
C99  0.1uF  [C402-25]  23.88 124.59 0 top
C100  0.01uF  [C402-25]  23.88 123.44 0 top
C101  0.01uF  [C402-25]  32 122.94 180 top
C102  10uF  [C603-35X45]  92.46 122.81 270 top
C103  0.01uF  [C402-25]  23.88 122.43 0 top
C104  0.01uF  [C402-25]  91.06 122.43 270 top
C105  0.01uF  [C402-25]  32 121.92 180 top
C106  0.01uF  [C402-25]  23.88 121.41 0 top
C107  0.01uF  [C402-25]  23.88 120.4 0 top
C108  0.01uF  [C402-25]  32 120.4 180 top
C109  100uF  [C7343-84X118]  150.5 120.27 0 top
C110  0.01uF  [C402-25]  32 119.25 180 top
C111  0.01uF  [C402-25]  23.88 119.13 0 top
C112  0.01uF  [C402-25]  27.18 118.87 90 top
C113  0.01uF  [C402-25]  28.19 118.87 90 top
C114  0.01uF  [C402-25]  29.21 118.87 90 top
C115  0.1uF  [C402-25]  30.48 118.87 90 top
C116  0.01uF  [C402-25]  20.57 118.11 180 top
C117  100uF  [C7343-84X118]  150.5 115.19 0 top
C118  2.2uF  [C603-35X45]  33.66 100.71 90 top
C119  100uF  [C7343-84X118]  150.5 110.11 0 top
C120  0.1uF  [C402-25]  101.47 108.84 180 top
C121  NP  [C402-25]  29.84 103.89 180 top
C122  0.1uF  [C402-25]  139.95 107.7 0 top
C123  0.1uF  [C402-25]  116.59 107.31 0 top
C124  2.2uF  [C603-35X45]  28.96 100.58 90 top
C125  NP  [C1210-70X102]  191.13 105.28 0 top
C126  100uF  [C7343-84X118]  153.67 102.23 90 top
C127  100uF  [C7343-84X118]  158.75 102.23 90 top
C128  100pF  [C603-35X45]  167.51 102.23 180 top
C129  100pF  [C603-35X45]  178.31 100.33 0 top
C130  10nF  [C402-25]  51.18 100.2 0 top
C131  47uF  [C1210-C7343-DUAL]  190.37 100.2 0 top
C132  10nF  [C402-25]  51.18 98.93 0 top
C133  10nF  [C402-25]  51.18 96.39 0 top
C134  10nF  [C402-25]  51.18 95.12 0 top
C135  0.1uF  [C402-25]  155.83 94.74 0 top
C136  47uF  [C1210-C7343-DUAL]  190.37 93.85 0 top
C137  0.1uF  [C402-25]  94.87 90.55 0 top
C138  0.1uF  [C402-25]  111.38 90.55 0 top
C139  0.1uF  [C402-25]  132.59 85.72 180 top
C140  10uF  [C805-35X60]  90.17 82.02 0 top
C141  10uF  [C805-35X60]  105.41 81 0 top
C142  0.1uF  [C201-6P6SPC]  16.64 80.26 180 top
C143  47uF  [C1210-70X102]  167.51 80.14 270 top
C144  0.1uF  [C201-6P6SPC]  16.64 79.5 180 top
C145  10uF  [C805-35X60]  95.89 79.98 0 top
C146  47uF  [C1210-70X102]  173.1 77.09 180 top
C147  10uF  [C805-35X60]  79.25 73.25 180 top
C148  47uF  [C1210-70X102]  154.18 76.96 0 top
C149  4.7uF  [C805-35X60]  95.89 77.95 0 top
C150  0.1uF  [C402-25]  111.76 70.99 90 top
C151  0.1uF  [C402-25]  95.5 76.45 0 top
C152  0.1uF  [C402-25]  95.5 75.18 0 top
C153  22uF  [C1206-40X70]  135.13 68.45 180 top
C154  22uF  [C1206-40X70]  139.95 68.45 0 top
C155  10uF  [C805-35X60]  113.54 71.73 90 top
C156  10uF  [C805-35X60]  133.6 65.28 90 top
C157  10uF  [C805-35X60]  141.6 65.28 90 top
C158  47uF  [C1210-70X102]  154.18 63.5 0 top
C159  1uF  [C603-35X45]  46.23 51.31 180 top
C160  47uF  [C1210-70X102]  170.43 60.83 90 top
C161  10uF  [C805-35X60]  142.62 60.07 270 top
C162  10uF  [C805-35X60]  110.74 59.79 270 top
C163  10uF  [C805-35X60]  114.17 59.79 270 top
C164  0.22uF  [C603-35X45]  50.8 49.78 0 top
C165  2.2uF  [C603-35X45]  50.8 52.83 180 top
C166  0.1uF  [C402-25]  152.4 54.86 0 top
C167  10uF  [C805-35X60]  133.48 54.86 270 top
C168  10uF  [C805-35X60]  141.6 54.86 270 top
C169  22uF  [C1206-40X70]  135.13 51.69 180 top
C170  22uF  [C1206-40X70]  139.95 51.69 0 top
C171  10uF  [C1206-40X70-POL]  172.59 50.93 90 top
C172  10uF  [C805-35X60]  69.09 51.66 180 top
C173  10uF  [C805-35X60]  114.17 50.65 270 top
C174  10uF  [C805-35X60]  117.6 50.65 270 top
C175  0.1uF  [C402-25]  168.53 50.42 270 top
C176  0.1uF  [C402-25]  174.5 49.66 90 top
C177  0.1uF  [C402-25]  152.4 48.01 0 top
C178  4.7uF  [C603-35X45]  182.12 46.61 90 top
C179  0.1uF  [C402-25]  180.47 46.35 90 top
C180  0.1uF  [C201-6P6SPC]  74.42 40.89 180 bottom
C181  0.47uF  [C402-25]  86.87 40.51 270 bottom
C182  0.47uF  [C402-25]  92.58 40.51 270 bottom
C183  0.1uF  [C402-25]  180.21 40.77 90 top
C184  0.1uF  [C402-25]  181.23 40.77 90 top
C185  10uF  [C1206-40X70-POL]  183.13 40.26 90 top
C186  0.47uF  [C402-25]  102.11 40.51 270 top
C187  0.47uF  [C402-25]  96.39 40.51 270 bottom
C188  0.1uF  [C402-25]  119.25 39.5 0 top
C189  1uF  [C508-18X70]  87.12 35.05 180 bottom
C190  0.1uF  [C402-25]  177.67 36.07 270 top
C191  10uF  [C1206-40X70-POL]  179.58 35.56 270 top
C192  0.1uF  [C402-25]  185.42 35.43 270 top
C193  10uF  [C805-35X60]  87.12 35.05 180 top
C194  0.22uF  [C201-6P6SPC]  115.44 32.26 90 top
C195  0.22uF  [C201-6P6SPC]  110.36 32.26 90 top
C196  0.22uF  [C201-6P6SPC]  125.09 32.26 90 bottom
C197  10uF  [C805-35X60]  97.79 35.69 180 top
C198  0.22uF  [C201-6P6SPC]  112.39 32.26 90 bottom
C199  0.22uF  [C201-6P6SPC]  126.87 32.26 90 top
C200  0.1uF  [C402-25]  97.79 27.69 180 bottom
C201  0.22uF  [C201-6P6SPC]  122.17 25.53 90 bottom
C202  0.47uF  [C402-25]  100.46 24.38 0 top
C203  2.2uF  [C603-35X45]  183.51 27.94 270 top
C204  0.22uF  [C402-25]  140.72 18.03 0 top
C205  0.22uF  [C402-25]  140.72 23.24 0 top
C206  0.1uF  [C402-25]  170.31 27.43 90 top
C207  0.22uF  [C201-6P6SPC]  117.22 32.26 90 bottom
C208  0.22uF  [C402-25]  140.72 21.46 0 top
C209  0.47uF  [C402-25]  100.46 22.61 0 top
C210  0.47uF  [C402-25]  100.46 19.18 0 top
C211  3300pF  [C402-25]  152.91 23.11 180 bottom
C212  0.22uF  [C402-25]  140.72 19.81 0 top
C213  0.47uF  [C402-25]  100.46 20.95 0 top
C214  24pF  [C402-25]  152.4 25.65 270 bottom
C215  220pF  [C402-25]  153.42 25.65 270 bottom
C216  0.1uF  [C201-6P6SPC]  103.38 40.51 270 bottom
C217  0.1uF  [C402-25]  62.61 14.83 180 top
C218  10uF  [C603-35X45]  65.79 14.83 180 top
C219  0.1uF  [C402-25]  74.8 14.83 180 top
C220  10uF  [C603-35X45]  77.85 14.83 180 top
C221  0.22uF  [C402-25]  140.72 16.51 0 top
C222  0.22uF  [C402-25]  140.72 25.15 0 top
C223  10uF  [C603-35X45]  90.39 14.4 180 top
C224  0.47uF  [C402-25]  100.46 17.53 0 top
C225  0.47uF  [C402-25]  100.46 15.88 0 top
C226  0.1uF  [C402-25]  189.48 144.02 270 bottom
C227  0.1uF  [C402-25]  181.74 96.27 0 bottom
C228  0.1uF  [C402-25]  164.85 95.89 180 bottom
C229  0.1uF  [C402-25]  152.91 94.11 90 top
C230  0.1uF  [C402-25]  135 48.64 90 bottom
C231  0.1uF  [C402-25]  140.08 71.63 270 bottom
C232  0.1uF  [C402-25]  148.72 69.6 0 bottom
C233  0.1uF  [C402-25]  179.71 82.3 270 bottom
C234  0.1uF  [C402-25]  166.24 85.22 270 bottom
C235  0.1uF  [C402-25]  148.08 93.6 90 top
C236  0.1uF  [C402-25]  140.84 13.34 270 bottom
C237  0.1uF  [C402-25]  132.08 38.1 0 top
C238  0.1uF  [C402-25]  145.16 52.7 180 bottom
C239  0.1uF  [C402-25]  145.29 60.71 180 bottom
C240  0.1uF  [C402-25]  152.78 60.2 180 top
C241  0.1uF  [C402-25]  180.47 76.07 0 top
C242  0.1uF  [C402-25]  173.35 81.53 90 top
C243  0.1uF  [C402-25]  177.42 57.15 0 top
C244  0.1uF  [C402-25]  171.96 62.23 180 bottom
C245  0.1uF  [C402-25]  180.47 72.26 0 top
C246  0.1uF  [C402-25]  182.63 57.15 180 top
C247  0.1uF  [C402-25]  165.1 56.26 270 bottom
C248  0.1uF  [C402-25]  181.48 68.2 180 top
C249  0.1uF  [C402-25]  181.48 64.52 180 top
C250  0.1uF  [C402-25]  180.21 60.83 180 top
C251  0.1uF  [C402-25]  161.54 85.09 270 bottom
C252  0.1uF  [C402-25]  156.84 85.09 270 bottom
C254  10uF  [C603-35X45]  20.07 177.29 0 bottom
C255  10uF  [C603-35X45]  26.8 164.21 90 bottom
C256  0.1uF  [C402-25]  70.99 172.59 270 bottom
C257  0.01uF  [C402-25]  124.33 166.24 90 bottom
C258  0.01uF  [C402-25]  103.25 166.24 90 bottom
C259  0.1uF  [C402-25]  54.23 163.7 90 bottom
C260  0.1uF  [C402-25]  158.62 163.19 270 bottom
C261  0.1uF  [C402-25]  157.35 163.19 90 bottom
C262  0.1uF  [C402-25]  61.47 162.31 180 bottom
C263  0.1uF  [C402-25]  54.23 160.53 90 bottom
C264  0.1uF  [C402-25]  61.47 160.4 180 bottom
C265  0.1uF  [C402-25]  46.1 163.58 90 bottom
C266  0.1uF  [C402-25]  41.02 163.58 90 bottom
C267  0.1uF  [C402-25]  126.11 159.51 0 bottom
C268  NP-27 pF  [C603-35X45]  101.98 159.26 180 bottom
C269  5.6pF  [C402-25]  82.3 158.62 0 bottom
C270  0.1uF  [C402-25]  150.62 158.5 270 bottom
C271  0.1uF  [C402-25]  149.61 158.5 270 bottom
C272  0.1uF  [C402-25]  61.47 158.5 180 bottom
C273  NP  [C603-35X45]  119.25 157.99 270 bottom
C274  0.1uF  [C402-25]  54.23 157.35 90 bottom
C275  10uF  [C603-35X45]  82.3 157.1 0 bottom
C276  0.1uF  [C402-25]  61.47 156.59 180 bottom
C277  0.1uF  [C402-25]  148.97 155.57 0 bottom
C278  10uF  [C603-35X45]  123.19 153.67 270 bottom
C279  0.1uF  [C402-25]  168.28 152.4 90 bottom
C280  0.1uF  [C402-25]  146.3 151.76 0 bottom
C281  1000pF  [C402-25]  24 151.76 0 bottom
C282  0.1uF  [C402-25]  28.45 151.38 270 bottom
C283  0.01uF  [C402-25]  22.48 151.26 90 bottom
C284  NP-27 pF  [C603-35X45]  101.98 150.37 180 bottom
C285  0.1uF  [C402-25]  27.69 149.86 180 bottom
C286  0.1uF  [C402-25]  27.69 148.08 180 bottom
C287  10uF  [C603-35X45]  30.61 146.3 0 bottom
C288  0.1uF  [C402-25]  26.42 146.3 180 bottom
C289  5.6pF  [C402-25]  77.47 144.02 0 bottom
C290  0.1uF  [C402-25]  146.69 143.76 0 bottom
C291  0.1uF  [C402-25]  66.8 143.64 90 bottom
C292  1000pF  [C402-25]  162.69 143.26 90 bottom
C293  0.01uF  [C402-25]  161.67 143.26 90 bottom
C294  0.1uF  [C402-25]  160.66 143.26 90 bottom
C295  0.01uF  [C402-25]  159.64 143.26 90 bottom
C296  1000pF  [C402-25]  158.62 143.26 90 bottom
C297  0.1uF  [C402-25]  157.61 143.26 90 bottom
C298  10uF  [C603-35X45]  77.22 142.62 0 bottom
C299  NP-27 pF  [C603-35X45]  108.33 138.94 180 bottom
C300  22uF  [C1210-70X102]  177.8 135.76 90 bottom
C301  22uF  [C1210-70X102]  172.72 135.76 90 bottom
C302  0.22uF  [C402-25]  151.76 134.75 90 bottom
C303  2.2uF  [C603-35X45]  148.97 134.49 180 bottom
C304  0.1uF  [C402-25]  144.78 133.22 180 bottom
C305  0.1uF  [C402-25]  70.74 133.22 180 bottom
C306  2.2uF  [C603-35X45]  144.4 131.95 180 bottom
C307  4.7uF  [C603-35X45]  153.92 132.21 0 bottom
C308  1uF  [C603-35X45]  29.97 130.81 90 bottom
C309  1uF  [C603-35X45]  26.54 130.81 90 bottom
C310  0.22uF  [C402-25]  151.76 130.56 270 bottom
C311  NP-27 pF  [C603-35X45]  108.33 130.05 180 bottom
C312  0.01uF  [C402-25]  20.19 129.67 180 bottom
C313  0.1uF  [C402-25]  140.34 128.78 270 bottom
C314  1uF  [C603-35X45]  36.58 127.89 0 bottom
C315  1uF  [C603-35X45]  36.58 126.24 0 bottom
C316  0.1uF  [C402-25]  64.77 125.86 90 bottom
C317  10uF  [C603-35X45]  20.19 125.86 180 bottom
C318  33nF  [C402-25]  20.57 124.46 180 bottom
C319  33nF  [C402-25]  20.57 123.44 180 bottom
C320  0.1uF  [C201-6P6SPC]  213.74 132.59 90 bottom
C321  33nF  [C402-25]  20.57 122.43 180 bottom
C322  33nF  [C402-25]  20.57 121.41 180 bottom
C323  0.1uF  [C402-25]  146.05 120.02 90 bottom
C324  10uF  [C603-35X45]  20.19 119.76 180 bottom
C325  4.7uF  [C805-35X60]  180.47 119.51 270 bottom
C326  0.1uF  [C402-25]  210.06 129.67 270 bottom
C327  10uF  [C603-35X45]  36.58 119.38 0 bottom
C328  0.01uF  [C402-25]  17.02 118.87 180 bottom
C329  0.1uF  [C402-25]  121.79 118.49 270 bottom
C330  1uF  [C603-35X45]  20.19 118.11 180 bottom
C331  0.1uF  [C402-25]  60.71 116.46 90 bottom
C332  0.01uF  [C402-25]  20.19 115.82 180 bottom
C333  0.22uF  [C603-35X45]  179.07 115.57 90 bottom
C334  0.22uF  [C603-35X45]  171.45 115.57 90 bottom
C335  0.1uF  [C402-25]  128.65 115.57 0 bottom
C336  10uF  [C603-35X45]  28.32 115.32 270 bottom
C337  0.1uF  [C402-25]  16.64 113.79 90 bottom
C338  0.01uF  [C402-25]  179.07 112.65 270 bottom
C339  0.01uF  [C402-25]  171.45 112.65 270 bottom
C340  0.1uF  [C402-25]  12.57 112.65 0 bottom
C341  0.1uF  [C402-25]  202.82 81.03 90 bottom
C342  0.1uF  [C402-25]  15.62 111.12 90 bottom
C343  0.01uF  [C402-25]  171.45 110.49 0 bottom
C344  39pf  [C402-25]  184.15 109.86 180 bottom
C345  0.01uF  [C402-25]  179.32 109.86 180 bottom
C346  10uF  [C603-35X45]  31.75 109.22 180 bottom
C347  5.6pF  [C402-25]  31.5 107.82 180 bottom
C348  2700pF  [C402-25]  168.66 109.47 0 bottom
C349  2000pF  [C402-25]  182.63 109.35 90 bottom
C350  56pf  [C402-25]  169.16 107.95 90 bottom
C351  0.1uF  [C402-25]  136.91 107.7 0 bottom
C352  1000pF  [C402-25]  179.96 106.81 180 bottom
C353  0.1uF  [C402-25]  68.33 105.79 0 bottom
C354  0.1uF  [C402-25]  79.63 104.52 180 top
C355  0.1uF  [C402-25]  119.51 102.62 0 bottom
C356  0.1uF  [C402-25]  123.57 102.62 0 bottom
C357  0.1uF  [C402-25]  203.07 69.47 90 bottom
C358  220pF  [C402-25]  150.5 97.92 0 bottom
C359  0.1uF  [C402-25]  74.8 91.19 270 bottom
C360  0.1uF  [C402-25]  135.64 91.06 0 bottom
C361  0.1uF  [C402-25]  91.82 90.55 0 bottom
C362  0.1uF  [C402-25]  108.97 90.55 0 bottom
C363  0.1uF  [C402-25]  77.98 59.69 180 bottom
C364  1uF  [C402-25]  74.55 72.77 90 bottom
C365  0.1uF  [C402-25]  148.34 83.44 180 top
C366  0.1uF  [C402-25]  142.54 84.96 90 bottom
C367  1uF  [C402-25]  74.55 68.33 90 bottom
C368  0.1uF  [C402-25]  77.98 61.09 180 bottom
C369  1uF  [C508-18X70]  90.3 82.02 0 bottom
C370  1uF  [C402-25]  71.5 68.33 90 bottom
C371  0.1uF  [C402-25]  77.98 58.17 180 bottom
C372  1uF  [C508-18X70]  104.39 78.08 0 top
C373  1uF  [C508-18X70]  106.55 78.08 0 top
C374  1uF  [C508-18X70]  90.17 78.61 0 top
C375  4.7uF  [C805-35X60]  164.34 76.96 270 bottom
C376  2.2uF  [C603-35X45]  162.43 76.96 270 bottom
C377  2.2uF  [C603-35X45]  160.66 76.96 270 bottom
C378  1uF  [C402-25]  79.76 72.87 180 bottom
C379  0.1uF  [C201-6P6SPC]  112.65 75.44 0 bottom
C380  0.1uF  [C201-6P6SPC]  110.11 75.44 180 bottom
C381  0.1uF  [C402-25]  11.94 12.7 180 top
C382  1uF  [C508-18X70]  90.17 75.06 0 top
C383  1uF  [C508-18X70]  104.39 74.4 0 top
C384  1uF  [C508-18X70]  106.55 74.4 0 top
C385  2.2uF  [C603-35X45]  161.16 73.53 0 bottom
C386  1uF  [C402-25]  68.45 68.33 90 bottom
C387  0.47uF  [C402-25]  77.98 54.74 180 bottom
C388  1uF  [C402-25]  71.5 72.77 90 bottom
C389  0.1uF  [C402-25]  77.98 56.77 180 bottom
C390  4.7uF  [C805-35X60]  167.26 73.28 0 bottom
C391  0.47uF  [C402-25]  101.85 71.35 90 bottom
C392  0.1uF  [C402-25]  100.71 71.35 90 bottom
C393  0.1uF  [C402-25]  99.31 71.35 90 bottom
C394  0.1uF  [C402-25]  97.92 71.35 90 bottom
C395  0.1uF  [C402-25]  96.65 71.35 90 bottom
C396  0.47uF  [C402-25]  95.5 72.64 90 top
C397  0.1uF  [C402-25]  94.36 71.35 90 bottom
C398  0.1uF  [C402-25]  92.96 71.35 90 bottom
C399  0.1uF  [C402-25]  91.82 71.35 90 bottom
C400  0.1uF  [C402-25]  90.55 72.39 90 top
C401  0.1uF  [C402-25]  88.01 71.35 90 bottom
C402  4.7uF  [C805-35X60]  159.64 69.6 180 bottom
C403  2.2uF  [C603-35X45]  187.71 62.74 0 top
C404  2.2uF  [C603-35X45]  188.72 68.2 180 top
C405  0.1uF  [C402-25]  120.27 41.66 270 bottom
C406  2.2uF  [C603-35X45]  171.32 69.09 180 bottom
C407  2.2uF  [C603-35X45]  167.51 68.71 0 bottom
C408  100nF  [C402-25]  160.27 68.07 0 bottom
C409  4.7uF  [C805-35X60]  158.88 66.55 180 bottom
C410  2.2uF  [C603-35X45]  171.32 67.44 180 bottom
C411  1uF  [C508-18X70]  109.35 69.72 90 top
C412  2.2uF  [C603-35X45]  167.51 67.06 0 bottom
C413  100nF  [C402-25]  162.81 66.55 270 bottom
C414  2.2uF  [C603-35X45]  164.34 66.17 90 bottom
C415  0.1uF  [C402-25]  17.53 64.77 180 bottom
C416  0.1uF  [C402-25]  15.49 64.77 0 bottom
C417  10uF  [C805-35X60]  162.43 63.12 270 bottom
C418  10uF  [C805-35X60]  160.4 63.12 270 bottom
C419  0.1uF  [C402-25]  15.24 63.12 270 bottom
C420  4.7uF  [C805-35X60]  166.75 63.5 90 bottom
C421  0.47uF  [C402-25]  97 62.71 0 bottom
C422  0.1uF  [C402-25]  94.59 62.71 180 bottom
C423  2.2uF  [C603-35X45]  164.34 62.61 270 bottom
C424  0.1uF  [C402-25]  107.19 62.59 0 bottom
C425  0.47uF  [C402-25]  89 62.64 180 bottom
C426  0.47uF  [C402-25]  91.08 62.36 90 bottom
C427  0.1uF  [C402-25]  87.1 62.36 90 bottom
C428  1uF  [C508-18X70]  114.17 62.36 270 top
C429  0.1uF  [C402-25]  17.14 25.65 180 top
C430  0.1uF  [C402-25]  11.18 25.4 180 top
C431  0.1uF  [C402-25]  107.19 61.19 0 bottom
C432  0.1uF  [C402-25]  92.58 61.19 270 bottom
C433  0.47uF  [C402-25]  95.38 61.06 0 bottom
C434  0.1uF  [C402-25]  88.16 61.06 180 bottom
C435  0.47uF  [C402-25]  90.3 60.78 90 bottom
C436  0.1uF  [C402-25]  86.11 60.78 270 bottom
C437  1uF  [C402-25]  98.17 60.78 90 bottom
C438  0.47uF  [C402-25]  107.19 60.05 0 bottom
C439  1uF  [C508-18X70]  114.17 59.66 270 bottom
C440  1uF  [C508-18X70]  110.74 59.66 270 bottom
C441  0.47uF  [C402-25]  89 59.66 180 bottom
C442  1uF  [C402-25]  98.86 59.16 270 bottom
C443  1uF  [C402-25]  96.27 59.16 225 bottom
C444  0.1uF  [C402-25]  94.87 59.16 270 bottom
C445  0.1uF  [C402-25]  85.8 59.08 225 bottom
C446  0.47uF  [C402-25]  107.19 58.9 0 bottom
C447  0.47uF  [C402-25]  92.58 58.9 270 bottom
C448  0.47uF  [C402-25]  88.16 58.78 180 bottom
C449  1uF  [C402-25]  90.58 58.65 0 bottom
C450  1uF  [C402-25]  121.16 58.39 90 bottom
C451  1uF  [C402-25]  97 58.01 180 bottom
C452  0.47uF  [C402-25]  107.19 57.63 0 bottom
C453  0.1uF  [C402-25]  18.03 57.4 0 bottom
C454  0.1uF  [C402-25]  15.88 57.4 180 bottom
C455  1uF  [C508-18X70]  114.17 57.15 270 top
C456  1uF  [C508-18X70]  110.74 57.15 270 top
C457  NP-18pF  [C402-25]  69.22 57.25 270 bottom
C458  0.1uF  [C402-25]  51.05 46.23 0 bottom
C459  0.47uF  [C402-25]  92.58 56.74 270 bottom
C460  0.1uF  [C402-25]  87.12 56.49 0 bottom
C461  0.1uF  [C402-25]  107.19 53.95 0 bottom
C462  0.47uF  [C402-25]  98.17 56.36 0 bottom
C463  0.1uF  [C402-25]  96.27 56.36 0 bottom
C464  0.1uF  [C402-25]  94.36 56.36 180 bottom
C465  1uF  [C402-25]  90.93 56.36 0 bottom
C466  0.47uF  [C402-25]  89.03 56.36 180 bottom
C467  220pF  [C402-25]  204.85 55.63 90 bottom
C468  220pF  [C402-25]  195.58 55.5 90 bottom
C469  1uF  [C402-25]  121.16 51.41 90 bottom
C470  0.1uF  [C402-25]  9.02 18.41 90 bottom
C471  0.1uF  [C402-25]  10.29 55.12 0 bottom
C472  0.1uF  [C402-25]  96.16 54.84 0 bottom
C473  1uF  [C402-25]  92.61 54.76 90 bottom
C474  NP-18pF  [C402-25]  69.22 54.71 90 bottom
C475  1uF  [C402-25]  88.14 54.43 225 bottom
C476  0.1uF  [C402-25]  99.06 54.36 270 bottom
C477  1uF  [C402-25]  89.79 54.08 180 bottom
C478  1uF  [C402-25]  96.16 53.85 180 bottom
C479  NP-6.8pF  [C402-25]  53.72 54.23 0 bottom
C480  NP-6.8pF  [C402-25]  53.72 48.39 0 bottom
C481  1uF  [C402-25]  98.07 53.57 270 bottom
C482  0.47uF  [C402-25]  94.23 53.57 90 bottom
C483  0.1uF  [C402-25]  107.19 56.36 0 bottom
C484  1uF  [C508-18X70]  115.44 53.21 270 top
C485  1uF  [C508-18X70]  112.01 53.21 270 top
C486  1uF  [C402-25]  92.56 52.88 90 bottom
C487  0.47uF  [C402-25]  90.93 52.78 90 bottom
C488  0.1uF  [C402-25]  208.66 52.45 270 bottom
C489  0.47uF  [C402-25]  89 52.43 180 bottom
C490  0.1uF  [C402-25]  199.39 52.32 270 bottom
C491  0.47uF  [C402-25]  108.33 53.09 0 top
C492  0.47uF  [C402-25]  94.61 52.04 225 bottom
C493  0.1uF  [C402-25]  86.87 51.97 270 bottom
C494  1uF  [C402-25]  97 51.99 315 bottom
C495  0.47uF  [C402-25]  77.22 50.52 180 bottom
C496  1uF  [C402-25]  121.16 55.22 90 bottom
C497  1uF  [C508-18X70]  73.53 51.41 270 bottom
C498  0.47uF  [C402-25]  90.17 51.16 270 bottom
C499  0.47uF  [C402-25]  108.33 51.94 0 top
C500  1uF  [C402-25]  92.56 50.9 270 bottom
C501  0.47uF  [C402-25]  88.16 50.77 0 bottom
C502  0.1uF  [C402-25]  77.22 49.25 180 bottom
C503  1uF  [C508-18X70]  117.6 50.52 270 bottom
C504  1uF  [C508-18X70]  114.17 50.52 270 bottom
C505  1uF  [C508-18X70]  110.74 50.55 270 top
C506  0.47uF  [C402-25]  96.14 50.39 45 bottom
C507  1uF  [C402-25]  185.29 50.04 180 bottom
C508  0.1uF  [C402-25]  107.19 49.63 0 bottom
C509  0.47uF  [C402-25]  94.23 49.58 270 bottom
C510  1uF  [C402-25]  97.51 49.53 270 bottom
C511  0.1uF  [C402-25]  77.22 47.98 180 bottom
C512  0.47uF  [C402-25]  90.55 49.25 180 bottom
C513  0.47uF  [C402-25]  88.65 49.25 180 bottom
C514  0.1uF  [C402-25]  17.53 49.15 180 bottom
C515  0.1uF  [C402-25]  15.49 49.15 0 bottom
C516  1uF  [C508-18X70]  73.53 49.25 270 bottom
C517  NP-18pF  [C402-25]  66.29 49 90 bottom
C518  NP-18pF  [C402-25]  56.13 49 270 bottom
C519  0.1uF  [C402-25]  77.22 51.79 180 bottom
C520  0.1uF  [C402-25]  15.24 47.5 270 bottom
C521  1uF  [C402-25]  116.08 47.47 90 bottom
C522  0.1uF  [C402-25]  203.2 45.59 270 bottom
C523  0.1uF  [C402-25]  198.75 45.59 270 bottom
C524  0.1uF  [C402-25]  195.58 45.59 270 bottom
C525  0.1uF  [C402-25]  213.23 45.47 90 bottom
C526  1uF  [C402-25]  74.96 42.93 180 bottom
C529  0.1uF  [C402-25]  3.56 41.78 180 bottom
C530  0.1uF  [C402-25]  163.96 41.66 0 bottom
C531  0.1uF  [C402-25]  109.09 41.27 270 bottom
C532  0.1uF  [C402-25]  203.84 40.89 180 bottom
C533  0.47uF  [C402-25]  88.9 40.51 270 top
C534  0.47uF  [C402-25]  84.96 40.51 270 bottom
C535  0.47uF  [C402-25]  83.06 40.51 270 bottom
C536  0.47uF  [C402-25]  90.68 40.51 270 top
C537  0.47uF  [C402-25]  100.2 40.51 270 top
C538  0.47uF  [C402-25]  98.3 40.51 270 top
C539  0.47uF  [C402-25]  94.49 40.51 270 bottom
C540  0.1uF  [C402-25]  178.31 39.5 90 bottom
C541  0.1uF  [C402-25]  174.5 39.5 90 bottom
C542  0.1uF  [C402-25]  173.23 39.5 90 bottom
C543  0.1uF  [C402-25]  205.74 87 180 bottom
C544  0.1uF  [C402-25]  166.5 39.37 0 bottom
C545  220pF  [C402-25]  133.86 37.85 270 bottom
C546  0.1uF  [C402-25]  5.84 37.21 270 bottom
C547  0.1uF  [C402-25]  213.23 37.08 90 bottom
C548  NP  [C402-25]  166.5 37.08 0 bottom
C549  0.1uF  [C402-25]  8.51 36.58 180 bottom
C550  10uF  [C603-35X45]  4.06 35.31 180 bottom
C551  1uF  [C508-18X70]  97.79 35.66 180 bottom
C552  5.6pF  [C402-25]  2.79 32.13 0 bottom
C553  0.1uF  [C402-25]  68.07 31.22 0 bottom
C554  0.1uF  [C402-25]  80.9 31.09 0 bottom
C555  1000pF  [C402-25]  14.48 29.84 0 bottom
C556  0.22uF  [C201-6P6SPC]  129.92 32.26 90 bottom
C557  0.22uF  [C201-6P6SPC]  120.02 29.84 90 bottom
C558  0.1uF  [C402-25]  88.77 24 0 bottom
C559  0.47uF  [C402-25]  72.64 30.33 180 bottom
C560  0.1uF  [C402-25]  59.94 30.33 180 bottom
C561  0.22uF  [C201-6P6SPC]  131.95 32.26 90 top
C562  0.22uF  [C201-6P6SPC]  115.32 32.26 90 bottom
C563  10uF  [C805-35X60]  148.84 30.99 0 bottom
C564  1000pF  [C402-25]  4.7 29.84 0 bottom
C565  0.1uF  [C402-25]  81.79 29.18 90 bottom
C566  0.47uF  [C402-25]  69.09 29.18 90 bottom
C567  0.22uF  [C201-6P6SPC]  120.02 27.69 90 bottom
C568  0.22uF  [C201-6P6SPC]  130.05 32.26 90 top
C569  0.22uF  [C201-6P6SPC]  122.17 29.84 90 bottom
C570  0.22uF  [C201-6P6SPC]  110.49 32.26 90 bottom
C571  0.1uF  [C402-25]  72.64 28.8 180 bottom
C572  0.47uF  [C402-25]  59.94 28.8 180 bottom
C573  0.1uF  [C402-25]  93.31 28.75 180 bottom
C574  0.47uF  [C402-25]  86.96 28.75 180 bottom
C575  10uF  [C805-35X60]  145.03 28.7 180 bottom
C576  0.1uF  [C402-25]  212.6 28.32 180 bottom
C577  0.1uF  [C402-25]  197.23 30.1 0 bottom
C578  0.1uF  [C402-25]  137.92 28.19 180 bottom
C579  2.2uF  [C603-35X45]  1.52 27.69 90 bottom
C580  10uF  [C805-35X60]  148.84 28.96 0 bottom
C581  0.47uF  [C402-25]  81.79 27.15 270 bottom
C582  0.47uF  [C402-25]  69.09 27.15 270 bottom
C583  0.1uF  [C402-25]  85.85 26.9 90 bottom
C584  0.47uF  [C402-25]  94.58 26.84 270 bottom
C585  0.47uF  [C402-25]  73.15 26.77 90 bottom
C586  0.47uF  [C402-25]  60.45 26.77 90 bottom
C587  0.22uF  [C603-35X45]  153.03 28.57 0 bottom
C588  0.1uF  [C402-25]  91.4 25.95 90 bottom
C589  0.22uF  [C201-6P6SPC]  124.97 32.26 90 top
C590  0.22uF  [C201-6P6SPC]  107.82 27.69 90 bottom
C591  0.47uF  [C402-25]  79.5 25.63 270 bottom
C592  0.1uF  [C402-25]  66.8 25.5 270 bottom
C593  0.1uF  [C402-25]  211.33 24.77 180 bottom
C594  33uF  [C1206-40X70P]  193.55 25.15 270 bottom
C595  0.1uF  [C402-25]  81.79 25.12 90 bottom
C596  0.47uF  [C402-25]  69.09 25.12 90 bottom
C597  0.47uF  [C402-25]  94.58 24.94 90 bottom
C598  0.47uF  [C402-25]  85.22 24.74 180 bottom
C599  0.47uF  [C402-25]  72.52 24.74 180 bottom
C600  0.47uF  [C402-25]  59.82 24.74 180 bottom
C601  75pF  [C402-25]  150.11 22.48 270 top
C602  0.22uF  [C402-25]  140.72 16.64 0 bottom
C603  1uF  [C603-35X45]  144.65 25.02 90 bottom
C604  0.47uF  [C402-25]  100.46 24.51 0 bottom
C605  0.22uF  [C201-6P6SPC]  134.37 25.4 90 bottom
C606  0.22uF  [C201-6P6SPC]  120.02 25.53 90 bottom
C607  0.22uF  [C201-6P6SPC]  122.17 23.5 90 bottom
C608  0.22uF  [C201-6P6SPC]  107.82 29.84 90 bottom
C609  0.1uF  [C402-25]  202.31 28.83 0 bottom
C610  0.1uF  [C603-35X45]  144.65 22.23 90 bottom
C611  0.22uF  [C402-25]  140.72 21.59 0 bottom
C612  0.47uF  [C402-25]  82.3 21.56 0 bottom
C613  0.47uF  [C402-25]  69.6 21.56 0 bottom
C614  0.22uF  [C201-6P6SPC]  131.83 32.26 90 bottom
C615  0.22uF  [C201-6P6SPC]  117.35 32.26 90 top
C616  0.47uF  [C402-25]  100.46 22.73 0 bottom
C617  0.47uF  [C402-25]  95.12 20.07 0 bottom
C618  0.47uF  [C402-25]  85.22 19.91 180 bottom
C619  0.1uF  [C402-25]  82.42 19.91 0 bottom
C620  0.47uF  [C402-25]  72.52 19.91 180 bottom
C621  0.1uF  [C402-25]  69.72 19.91 0 bottom
C622  0.47uF  [C402-25]  59.82 19.91 180 bottom
C623  4700pF  [C402-25]  204.85 25.91 0 bottom
C624  4700pF  [C402-25]  213.74 19.3 270 bottom
C625  0.22uF  [C402-25]  140.72 25.27 0 bottom
C626  0.1uF  [C603-35X45]  149.35 20.45 0 bottom
C627  0.22uF  [C201-6P6SPC]  122.17 18.29 270 bottom
C628  0.22uF  [C201-6P6SPC]  107.82 18.29 270 bottom
C629  0.47uF  [C402-25]  95.12 18.16 0 bottom
C630  0.1uF  [C402-25]  85.22 18.39 180 bottom
C631  0.47uF  [C402-25]  82.42 18.39 0 bottom
C632  0.47uF  [C402-25]  72.52 18.39 180 bottom
C633  0.47uF  [C402-25]  69.72 18.39 0 bottom
C634  0.1uF  [C402-25]  59.82 18.39 180 bottom
C635  2.2uF  [C603-35X45]  173.99 18.29 270 bottom
C636  10uF  [C805-35X60]  149.35 18.54 0 bottom
C637  0.47uF  [C402-25]  100.46 16 0 bottom
C638  33uF  [C1206-40X70P]  184.78 19.05 270 bottom
C639  0.1uF  [C402-25]  163.19 17.91 90 bottom
C640  0.22uF  [C201-6P6SPC]  131.32 16.59 0 bottom
C641  0.22uF  [C201-6P6SPC]  116.97 16.59 0 bottom
C642  0.22uF  [C201-6P6SPC]  134.37 21.08 270 bottom
C643  0.22uF  [C201-6P6SPC]  120.02 21.08 270 bottom
C644  0.22uF  [C402-25]  140.72 19.94 0 bottom
C645  0.47uF  [C402-25]  100.46 17.65 0 bottom
C646  0.1uF  [C402-25]  25.78 49.02 0 bottom
C647  0.47uF  [C402-25]  90.81 21.72 180 bottom
C648  0.22uF  [C402-25]  140.72 18.16 0 bottom
C649  0.22uF  [C402-25]  140.72 23.37 0 bottom
C650  47uF  [C1210-70X102]  156.08 16.89 0 bottom
C651  47uF  [C1210-70X102]  151.13 14.1 270 bottom
C652  47uF  [C1210-70X102]  147.32 14.1 270 bottom
C653  0.47uF  [C402-25]  100.46 21.08 0 bottom
C654  0.47uF  [C402-25]  100.46 19.3 0 bottom
C655  0.1uF  [C402-25]  90.3 25.17 90 bottom
C656  0.22uF  [C201-6P6SPC]  133.73 13.84 270 bottom
C657  10uF  [C603-35X45]  131.95 13.84 0 bottom
C658  0.22uF  [C201-6P6SPC]  129.92 13.84 270 bottom
C659  0.22uF  [C201-6P6SPC]  129.16 13.84 270 bottom
C660  0.22uF  [C201-6P6SPC]  127.13 13.84 270 bottom
C661  0.22uF  [C201-6P6SPC]  126.36 13.84 270 bottom
C662  10uF  [C603-35X45]  124.33 13.84 180 bottom
C663  0.22uF  [C201-6P6SPC]  122.56 13.84 270 bottom
C664  0.22uF  [C201-6P6SPC]  119.38 13.84 270 bottom
C665  10uF  [C603-35X45]  117.6 13.84 0 bottom
C666  0.22uF  [C201-6P6SPC]  115.57 13.84 270 bottom
C667  0.22uF  [C201-6P6SPC]  114.81 13.84 270 bottom
C668  0.22uF  [C201-6P6SPC]  112.78 13.84 270 bottom
C669  0.22uF  [C201-6P6SPC]  112.01 13.84 270 bottom
C670  10uF  [C603-35X45]  109.98 13.84 180 bottom
C671  0.22uF  [C201-6P6SPC]  108.2 13.84 270 bottom
C672  0.22uF  [C201-6P6SPC]  107.82 19.94 270 bottom
C673  0.22uF  [C201-6P6SPC]  112.27 32.26 90 top
C674  0.22uF  [C201-6P6SPC]  120.02 18.67 270 bottom
C675  0.22uF  [C201-6P6SPC]  122.17 27.69 90 bottom
C676  0.22uF  [C201-6P6SPC]  134.37 29.84 90 bottom
C677  0.22uF  [C201-6P6SPC]  113.79 13.84 270 bottom
C678  0.22uF  [C201-6P6SPC]  107.82 23.5 90 bottom
C679  0.22uF  [C201-6P6SPC]  107.82 25.4 90 bottom
C680  0.22uF  [C201-6P6SPC]  110.03 16.51 180 bottom
C681  0.22uF  [C201-6P6SPC]  128.27 13.84 270 bottom
C682  0.22uF  [C201-6P6SPC]  124.76 16.51 0 bottom
C683  0.22uF  [C201-6P6SPC]  134.37 27.69 90 bottom
C684  0.22uF  [C201-6P6SPC]  134.37 18.67 270 bottom
C685  0.22uF  [C201-6P6SPC]  122.17 19.94 270 bottom
C686  0.22uF  [C201-6P6SPC]  127 32.26 90 bottom
C687  0.1uF  [C201-6P6SPC]  18.92 34.8 90 top
C688  0.1uF  [C201-6P6SPC]  20.19 34.8 90 top
C689  27 pF  [C402-25]  55.88 130.05 90 top
C690  27 pF  [C402-25]  52.07 130.05 90 top
C691  0.01uF  [C402-25]  48.77 125.6 270 bottom
C692  0.01uF  [C402-25]  47.24 121.28 0 bottom
C693  0.01uF  [C402-25]  49.02 116.97 90 bottom
C694  0.01uF  [C402-25]  54.1 116.97 90 bottom
C695  0.01uF  [C402-25]  55.88 118.75 180 bottom
C696  0.01uF  [C402-25]  55.88 122.05 180 bottom
C697  0.01uF  [C402-25]  52.83 125.6 270 bottom
C698  0.01uF  [C402-25]  54.23 125.6 270 bottom
C699  0.01uF  [C402-25]  55.88 123.06 180 bottom
C700  0.01uF  [C402-25]  55.88 121.03 180 bottom
C701  0.01uF  [C402-25]  50.29 125.6 270 bottom
C702  0.01uF  [C402-25]  47.24 124.08 0 bottom
C703  0.01uF  [C402-25]  47.24 118.24 0 bottom
C704  0.01uF  [C402-25]  51.05 116.97 90 bottom
C705  0.1uF  [C402-25]  162.05 157.35 270 bottom
C706  0.1uF  [C402-25]  128.52 105.66 90 bottom
C707  0.1uF  [C402-25]  125.6 105.66 90 bottom
C708  10uF  [C603-35X45]  47.5 114.05 270 top
C709  1uF  [C603-35X45]  50.55 111.51 270 top
C710  0.1uF  [C402-25]  167.13 51.05 90 top
C711  0.22uF  [C603-35X45]  196.98 132.59 90 bottom
C712  150pF  [C402-25]  198.5 127 270 bottom
C713  NP-0.1uF  [C402-25]  202.06 127 90 bottom
D1  NP  [SOD123-36X48]  204.22 163.32 180 top
D2  SMCJ14A-13-F  [SMC-80X128]  198.25 165.23 270 bottom
D3  SMCJ30A-13-F  [SMC-80X128]  189.61 161.04 0 bottom
D24  NP-6.2V  [SOD323]  197.61 127 270 top
DS1  LED_GRN  [LED1206-59X59]  214.12 173.99 270 top
DS2  LED_GRN  [LED1206-59X59]  214.38 69.47 0 top
DS3  LED_GRN  [LED1206-59X59]  214.38 67.44 0 top
DS4  LED_GRN  [LED1206-59X59]  214.38 65.41 0 top
DS5  LED_GRN  [LED1206-59X59]  214.38 63.37 0 top
